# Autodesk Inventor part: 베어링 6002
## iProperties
IsCustomPart: 0
Created: 2015-10
Part Number: 베어링 6002
Material: 강, 연강
Description: 깊은 그루브 볼 베어링
Document SubType Name: Modeling
Standard: KS B 2023
Designer: mdu
Standards Organization: KS
Language: ko-KR
Size Designation: 6002 - 15 x 32 x 9
Categories: <MemberInstance><Categories><Category DisplayName="샤프트 부품" InternalName="7f7aeb1f-a693-4053-b835-cee3144e0d98" Mnemonic="SHFT"><Category DisplayName="베어링" Inter
Density: 1 g/cm^3
Author: mdu
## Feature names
1. IDS_ARRAYBALL[SIMPL:T] [Circular Pattern]
